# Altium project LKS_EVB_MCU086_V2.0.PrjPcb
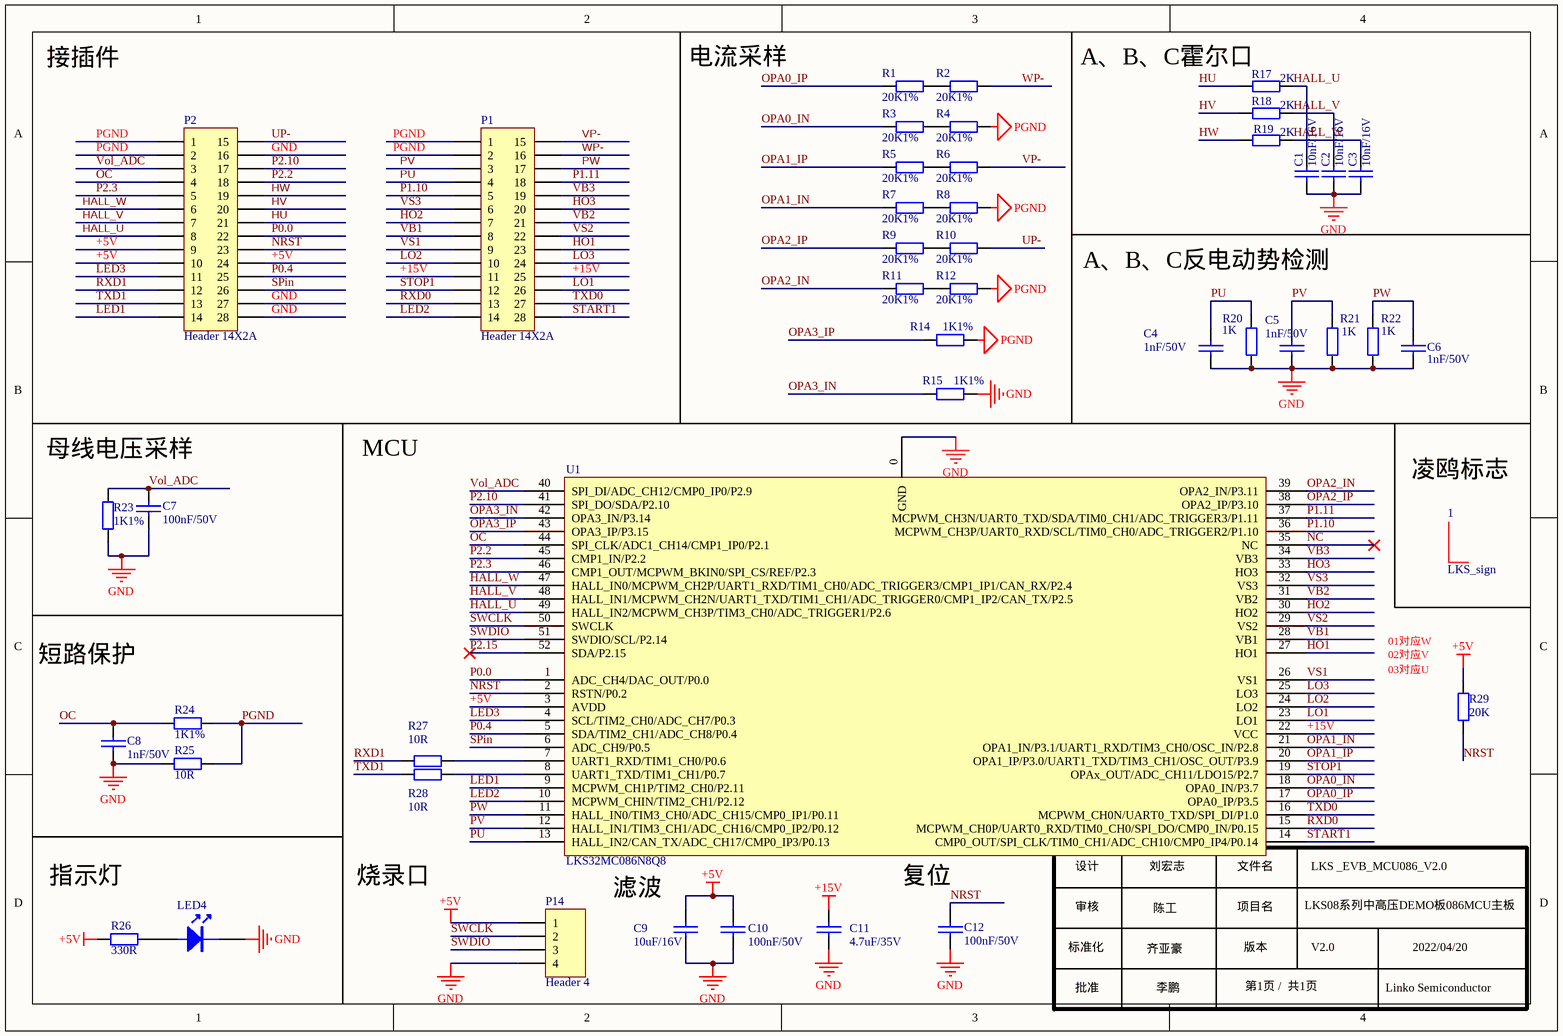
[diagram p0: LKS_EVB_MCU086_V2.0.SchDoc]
1 sheet, 45 parts. Net scope: global (net labels, ports and power ports of the same name join across sheets).
Board file: LKS_EVB_MCU086_V2.0.PcbDoc

## Sheet LKS_EVB_MCU086_V2.0.SchDoc
size A4; SheetNumber: 1; SheetTotal: 1

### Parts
1  LKS_sign  [LKS_LOGO2]
C1  10nF/16V  [0603C]
C2  10nF/16V  [0603C]
C3  10nF/16V  [0603C]
C4  1nF/50V  [0603C]
C5  1nF/50V  [0603C]
C6  1nF/50V  [0603C]
C7  100nF/50V  [0603C]
C8  1nF/50V  [0603C]
C9  10uF/16V  [0603C]
C10  100nF/50V  [0603C]
C11  4.7uF/35V  [0603C]
C12  100nF/50V  [0603C]
LED4  LED  [LED 0603R]  (value not drawn)
P1  Header 14X2A  [HDR 2X14 底层]
P2  Header 14X2A  [HDR 2X14 底层]
P14  Header 4  [HDR 1X4]
R1  20K1%  [0603R]
R2  20K1%  [0603R]
R3  20K1%  [0603R]
R4  20K1%  [0603R]
R5  20K1%  [0603R]
R6  20K1%  [0603R]
R7  20K1%  [0603R]
R8  20K1%  [0603R]
R9  20K1%  [0603R]
R10  20K1%  [0603R]
R11  20K1%  [0603R]
R12  20K1%  [0603R]
R14  1K1%  [0603R]
R15  1K1%  [0603R]
R17  2K  [0603R]
R18  2K  [0603R]
R19  2K  [0603R]
R20  1K  [0603R]
R21  1K  [0603R]
R22  1K  [0603R]
R23  1K1%  [0603R]
R24  1K1%  [0603R]
R25  10R  [0603R]
R26  330R  [0603R]
R27  10R  [0603R]
R28  10R  [0603R]
R29  20K  [0603R]
U1  LKS32MC086N8Q8  [QFN52]

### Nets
+5V: C9.2 C10.2 P2.9 P2.10 P2.24 P14.1 R26.1 R29.1 U1.3(AVDD)
+15V: C11.2 P1.11 P1.25 U1.22(VCC)
GND: C1.2 C2.2 C3.2 C4.2 C5.2 C6.2 C7.1 C8.1 C9.1 C10.1 C11.1 C12.2 LED4.2(K) P2.16 P2.27 P2.28 P14.4 R15.1 R20.2 R21.2 R22.2 R23.1 R25.2 U1.0(GND)
PGND: P1.1 P1.2 P2.1 P2.2 R4.1 R8.1 R12.1 R14.1 R24.2 R25.1
HALL_U: C1.1 P2.8 R17.2 U1.49(HALL_IN2/MCPWM_CH3P/TIM3_CH0/ADC_TRIGGER1/P2.6)
HALL_V: C2.1 P2.7 R18.2 U1.48(HALL_IN1/MCPWM_CH2N/UART1_TXD/TIM1_CH1/ADC_TRIGGER0/CMP1_IP2/CAN_TX/P2.5)
HALL_W: C3.1 P2.6 R19.2 U1.47(HALL_IN0/MCPWM_CH2P/UART1_RXD/TIM1_CH0/ADC_TRIGGER3/CMP1_IP1/CAN_RX/P2.4)
HO1: P1.23 U1.27(HO1)
HO2: P1.7 U1.30(HO2)
HO3: P1.20 U1.33(HO3)
HU: P2.21 R17.1
HV: P2.20 R18.1
HW: P2.19 R19.1
LED1: P2.14 U1.9(MCPWM_CH1P/TIM2_CH0/P2.11)
LED2: P1.14 U1.10(MCPWM_CHIN/TIM2_CH1/P2.12)
LED3: P2.11 U1.4(SCL/TIM2_CH0/ADC_CH7/P0.3)
LO1: P1.26 U1.23(LO1)
LO2: P1.10 U1.24(LO2)
LO3: P1.24 U1.25(LO3)
NC: U1.35(NC)
NRST: C12.1 P2.23 R29.2 U1.2(RSTN/P0.2)
OC: C8.2 P2.4 R24.1 U1.44(SPI_CLK/ADC1_CH14/CMP1_IP0/P2.1)
OPA0_IN: R3.2 U1.18(OPA0_IN/P3.7)
OPA0_IP: R1.2 U1.17(OPA0_IP/P3.5)
OPA1_IN: R7.2 U1.21(OPA1_IN/P3.1/UART1_RXD/TIM3_CH0/OSC_IN/P2.8)
OPA1_IP: R5.2 U1.20(OPA1_IP/P3.0/UART1_TXD/TIM3_CH1/OSC_OUT/P3.9)
OPA2_IN: R11.2 U1.39(OPA2_IN/P3.11)
OPA2_IP: R9.2 U1.38(OPA2_IP/P3.10)
OPA3_IN: R15.2 U1.42(OPA3_IN/P3.14)
OPA3_IP: R14.2 U1.43(OPA3_IP/P3.15)
P0.0: P2.22 U1.1(ADC_CH4/DAC_OUT/P0.0)
P0.4: P2.25 U1.5(SDA/TIM2_CH1/ADC_CH8/P0.4)
P1.10: P1.5 U1.36(MCPWM_CH3P/UART0_RXD/SCL/TIM0_CH0/ADC_TRIGGER2/P1.10)
P1.11: P1.18 U1.37(MCPWM_CH3N/UART0_TXD/SDA/TIM0_CH1/ADC_TRIGGER3/P1.11)
P2.2: P2.18 U1.45(CMP1_IN/P2.2)
P2.3: P2.5 U1.46(CMP1_OUT/MCPWM_BKIN0/SPI_CS/REF/P2.3)
P2.10: P2.17 U1.41(SPI_DO/SDA/P2.10)
P2.15: U1.52(SDA/P2.15)
PU: C4.1 P1.4 R20.1 U1.13(HALL_IN2/CAN_TX/ADC_CH17/CMP0_IP3/P0.13)
PV: C5.1 P1.3 R21.1 U1.12(HALL_IN1/TIM3_CH1/ADC_CH16/CMP0_IP2/P0.12)
PW: C6.1 P1.17 R22.1 U1.11(HALL_IN0/TIM3_CH0/ADC_CH15/CMP0_IP1/P0.11)
RXD0: P1.13 U1.15(MCPWM_CH0P/UART0_RXD/TIM0_CH0/SPI_DO/CMP0_IN/P0.15)
RXD1: P2.12 R27.2
SPin: P2.26 U1.6(ADC_CH9/P0.5)
START1: P1.28 U1.14(CMP0_OUT/SPI_CLK/TIM0_CH1/ADC_CH10/CMP0_IP4/P0.14)
STOP1: P1.12 U1.19(OPAx_OUT/ADC_CH11/LDO15/P2.7)
SWCLK: P14.2 U1.50(SWCLK)
SWDIO: P14.3 U1.51(SWDIO/SCL/P2.14)
TXD0: P1.27 U1.16(MCPWM_CH0N/UART0_TXD/SPI_DI/P1.0)
TXD1: P2.13 R28.1
UP-: P2.15 R10.1
VB1: P1.8 U1.28(VB1)
VB2: P1.21 U1.31(VB2)
VB3: P1.19 U1.34(VB3)
Vol_ADC: C7.2 P2.3 R23.2 U1.40(SPI_DI/ADC_CH12/CMP0_IP0/P2.9)
VP-: P1.15 R6.1
VS1: P1.9 U1.26(VS1)
VS2: P1.22 U1.29(VS2)
VS3: P1.6 U1.32(VS3)
WP-: P1.16 R2.1
NetLED4_1: LED4.1(A) R26.2
NetR1_1: R1.1 R2.2
NetR3_1: R3.1 R4.2
NetR5_1: R5.1 R6.2
NetR7_1: R7.1 R8.2
NetR9_1: R9.1 R10.2
NetR11_1: R11.1 R12.2
NetR27_1: R27.1 U1.7(UART1_RXD/TIM1_CH0/P0.6)
NetR28_2: R28.2 U1.8(UART1_TXD/TIM1_CH1/P0.7)

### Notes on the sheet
- 接插件
- 电流采样
- A、B、C霍尔口
- A、B、C反电动势检测
- 母线电压采样
- MCU
- (near 1) 凌鸥标志
- 01对应W
- 短路保护
- 02对应V
- (near R29) 03对应U
- 指示灯
- 烧录口
- 滤波
- (near U1) 复位
- (near U1) 设计
- 审核
- (near U1) 刘宏志
- 陈工
- (near U1) 文件名
- 项目名
- LKS08系列中高压DEMO板086MCU主板
- (near U1) LKS _EVB_MCU086_V2.0
- 标准化
- 批准
- 齐亚豪
- 李鹏
- 版本
- 第1页 /  共1页
- V2.0
- Linko Semiconductor
- 2022/04/20

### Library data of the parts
C1-C6 = CAP: Capacitor
C7-C12 = C: Capacitor
LED4 = LED: LED_Light
P1 P2 = Header 14X2A: Header, 14-Pin, Dual row
P14 = Header 4: Header, 4-Pin
R1-R12 R14 R15 R17-R24 R29 = Res: Resistor; Value: K
R25 = Res: Resistor; Value: 10
R26 = Res: Resistor; Value: 330
R27 = Res2: Resistor
R28 = Res2: Resistor; Value: 100R
U1 = LKS086N8Q8: 芯片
